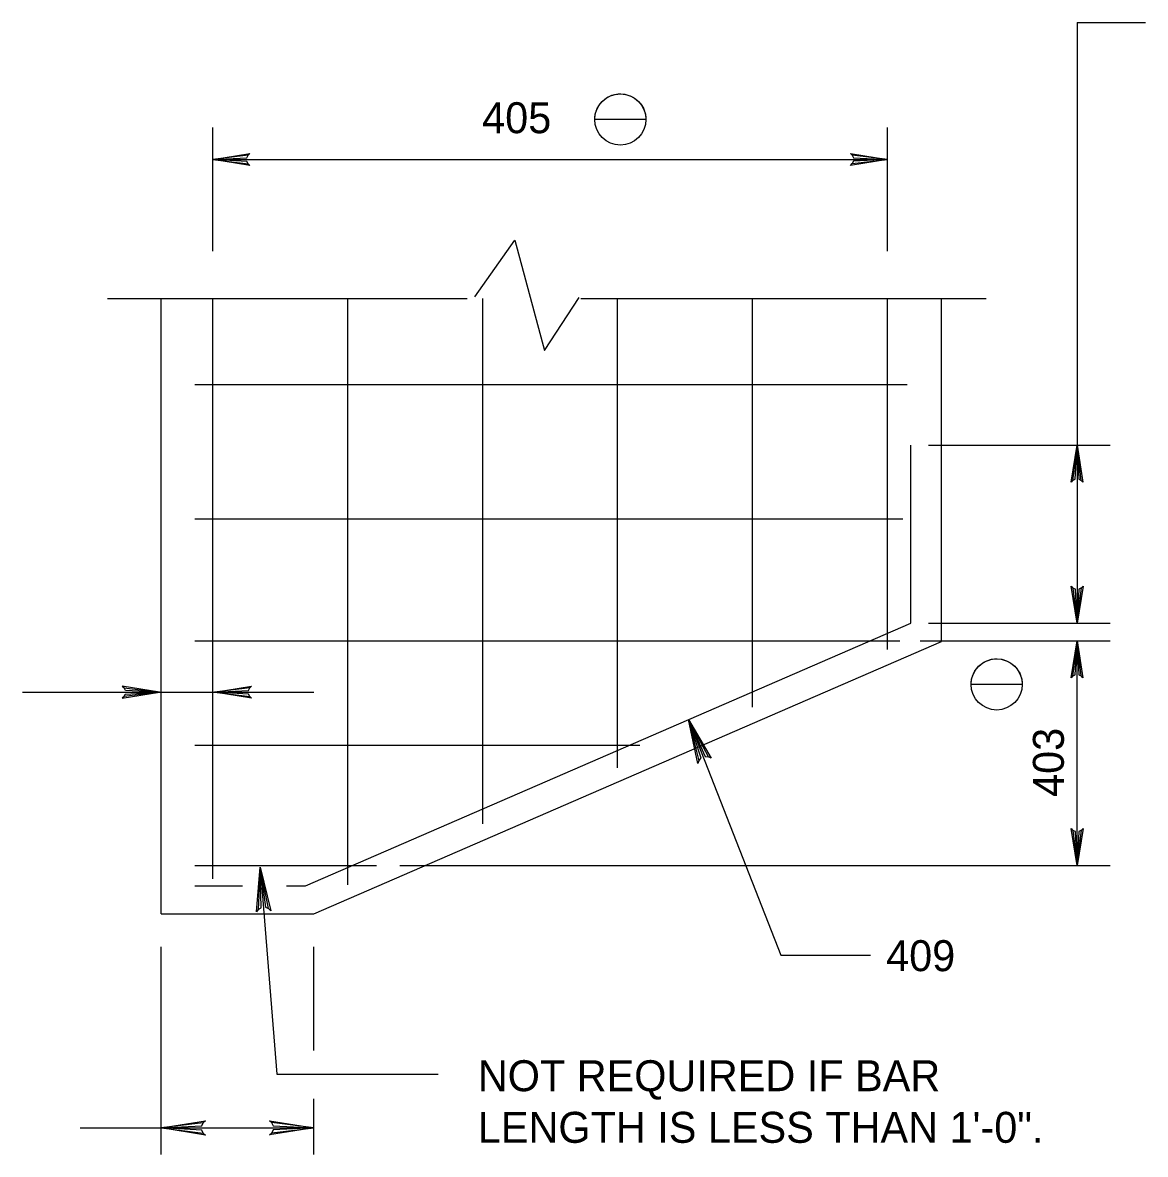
# Model space of a CAD drawing. Extents: x 637933 to 640019, y 298854 to 300042.
# Drawn here: x 638206.9 to 638315.7, y 299000 to 299109.6 of the extents above; entities that cross this region are included whole.
import ezdxf

# ---------------------------------------------------------------- set-up
doc = ezdxf.new("R2010")
doc.units = 0
doc.layers.add('1', color=7, linetype='Continuous')

msp = doc.modelspace()

# ---------------------------------------------------------------- linework, layer by layer
at = {"layer": '1'}
for p, q in [((638309.1, 299109.64), (638309.1, 299051.47)), ((638309.1, 299109.64), (638315.72, 299109.64)), ((638267.33, 299100.26), (638262.37, 299100.26)), ((638225.38, 299087.51), (638225.38, 299099.48)), ((638290.72, 299087.51), (638290.72, 299099.48)), ((638225.38, 299096.38), (638290.72, 299096.38)), ((638215.17, 299082.92), (638250, 299082.92)), ((638220.36, 299023.3), (638220.36, 299082.92)), ((638225.38, 299026.71), (638225.38, 299082.92)), ((638238.45, 299026.11), (638238.45, 299082.92)), ((638251.52, 299032.02), (638251.52, 299082.92)), ((638261.01, 299082.92), (638300.29, 299082.92)), ((638264.58, 299037.44), (638264.58, 299082.92)), ((638277.65, 299043.34), (638277.65, 299082.92)), ((638290.72, 299048.92), (638290.72, 299082.92)), ((638295.96, 299049.68), (638295.96, 299082.92)), ((638223.61, 299074.59), (638292.64, 299074.59)), ((638292.99, 299051.47), (638292.99, 299068.7)), ((638294.71, 299068.7), (638312.3, 299068.7)), ((638223.61, 299061.56), (638292.21, 299061.56)), ((638234.36, 299026.03), (638292.99, 299051.47)), ((638294.71, 299051.47), (638312.3, 299051.47)), ((638223.61, 299049.74), (638291.92, 299049.74)), ((638235.15, 299023.3), (638295.96, 299049.68)), ((638293.89, 299049.74), (638312.3, 299049.74)), ((638309.1, 299028), (638309.1, 299049.74)), ((638206.94, 299044.77), (638235.15, 299044.77)), ((638303.79, 299045.53), (638298.83, 299045.53)), ((638271.44, 299042.12), (638280.4, 299019.31)), ((638223.61, 299039.64), (638266.73, 299039.64)), ((638223.61, 299028), (638241.21, 299028)), ((638230, 299027.44), (638231.57, 299007.77)), ((638243.48, 299028), (638312.3, 299028)), ((638223.61, 299026.03), (638228.25, 299026.03)), ((638232.51, 299026.03), (638234.36, 299026.03)), ((638220.36, 299023.3), (638235.15, 299023.3)), ((638220.36, 299000), (638220.36, 299020.12)), ((638235.15, 299010.07), (638235.15, 299020.12)), ((638280.4, 299019.31), (638289.09, 299019.31)), ((638231.57, 299007.77), (638247.21, 299007.77)), ((638235.15, 299000), (638235.15, 299005.37)), ((638212.52, 299002.57), (638235.15, 299002.57))]:
    msp.add_line(p, q, dxfattribs=at)
for points in [[(638262.37, 299100.26), (638262.39, 299100.55), (638262.44, 299100.82), (638262.51, 299101.07), (638262.61, 299101.31), (638262.75, 299101.57), (638262.9, 299101.79), (638263.09, 299102.01), (638263.34, 299102.23), (638263.61, 299102.41), (638263.84, 299102.53), (638264.02, 299102.6), (638264.29, 299102.68), (638264.65, 299102.74), (638264.91, 299102.74), (638265.27, 299102.71), (638265.59, 299102.63), (638265.86, 299102.53), (638266.13, 299102.39), (638266.33, 299102.25), (638266.57, 299102.05), (638266.77, 299101.84), (638266.94, 299101.6), (638267.08, 299101.36), (638267.17, 299101.15), (638267.26, 299100.85), (638267.32, 299100.53), (638267.33, 299100.26)], [(638228.79, 299095.96), (638228.66, 299096.2), (638225.38, 299096.38), (638228.79, 299095.96), (638228.96, 299095.81), (638225.38, 299096.38), (638228.66, 299096.55), (638228.78, 299096.79), (638225.38, 299096.38), (638228.96, 299096.95), (638228.78, 299096.79)], [(638287.32, 299096.81), (638287.44, 299096.56), (638290.72, 299096.38), (638287.32, 299096.81), (638287.14, 299096.96), (638290.72, 299096.38), (638287.44, 299096.22), (638287.32, 299095.98), (638290.72, 299096.38), (638287.14, 299095.81), (638287.32, 299095.98)], [(638250.74, 299083.09), (638254.64, 299088.56), (638257.51, 299077.89), (638260.86, 299083.02)], [(638308.67, 299065.29), (638308.92, 299065.42), (638309.1, 299068.7), (638308.67, 299065.29), (638308.52, 299065.12), (638309.1, 299068.7), (638309.26, 299065.42), (638309.51, 299065.3), (638309.1, 299068.7), (638309.67, 299065.12), (638309.51, 299065.3)], [(638309.53, 299054.88), (638309.28, 299054.75), (638309.1, 299051.47), (638309.53, 299054.88), (638309.68, 299055.05), (638309.1, 299051.47), (638308.94, 299054.75), (638308.69, 299054.87), (638309.1, 299051.47), (638308.53, 299055.05), (638308.69, 299054.87)], [(638308.67, 299046.34), (638308.92, 299046.46), (638309.1, 299049.74), (638308.67, 299046.34), (638308.52, 299046.16), (638309.1, 299049.74), (638309.26, 299046.47), (638309.51, 299046.35), (638309.1, 299049.74), (638309.67, 299046.16), (638309.51, 299046.35)], [(638298.83, 299045.53), (638298.85, 299045.81), (638298.9, 299046.08), (638298.97, 299046.33), (638299.06, 299046.57), (638299.2, 299046.83), (638299.36, 299047.05), (638299.55, 299047.27), (638299.8, 299047.49), (638300.07, 299047.67), (638300.3, 299047.79), (638300.48, 299047.86), (638300.75, 299047.94), (638301.11, 299048), (638301.37, 299048), (638301.73, 299047.97), (638302.04, 299047.89), (638302.32, 299047.79), (638302.58, 299047.65), (638302.79, 299047.52), (638303.03, 299047.31), (638303.22, 299047.1), (638303.4, 299046.86), (638303.54, 299046.62), (638303.63, 299046.41), (638303.72, 299046.11), (638303.78, 299045.79), (638303.79, 299045.53)], [(638216.77, 299044.35), (638216.89, 299044.6), (638220.19, 299044.78), (638216.77, 299044.35), (638216.59, 299044.2), (638220.19, 299044.78), (638216.9, 299044.94), (638216.78, 299045.19), (638220.19, 299044.78), (638216.59, 299045.35), (638216.78, 299045.19)], [(638228.96, 299044.35), (638228.83, 299044.6), (638225.53, 299044.78), (638228.96, 299044.35), (638229.13, 299044.2), (638225.53, 299044.78), (638228.83, 299044.94), (638228.95, 299045.19), (638225.53, 299044.78), (638229.13, 299045.35), (638228.95, 299045.19)], [(638272.46, 299038.13), (638272.68, 299038.38), (638271.44, 299042.12), (638272.46, 299038.13), (638272.37, 299037.87), (638271.44, 299042.12), (638273.06, 299038.53), (638273.38, 299038.51), (638271.44, 299042.12), (638273.65, 299038.37), (638273.38, 299038.51)], [(638309.53, 299031.4), (638309.28, 299031.28), (638309.1, 299028), (638309.53, 299031.4), (638309.68, 299031.58), (638309.1, 299028), (638308.94, 299031.27), (638308.69, 299031.39), (638309.1, 299028), (638308.53, 299031.58), (638308.69, 299031.39)], [(638229.77, 299023.73), (638230.05, 299023.9), (638229.95, 299027.84), (638229.77, 299023.73), (638229.61, 299023.5), (638229.95, 299027.84), (638230.46, 299023.94), (638230.77, 299023.82), (638229.95, 299027.84), (638230.98, 299023.61), (638230.77, 299023.82)], [(638224.44, 299002.05), (638224.29, 299002.35), (638220.36, 299002.57), (638224.44, 299002.05), (638224.65, 299001.87), (638220.36, 299002.57), (638224.29, 299002.76), (638224.43, 299003.05), (638220.36, 299002.57), (638224.65, 299003.25), (638224.43, 299003.05)], [(638231.06, 299003.08), (638231.22, 299002.78), (638235.15, 299002.57), (638231.06, 299003.08), (638230.85, 299003.26), (638235.15, 299002.57), (638231.22, 299002.37), (638231.07, 299002.08), (638235.15, 299002.57), (638230.85, 299001.88), (638231.07, 299002.08)]]:
    msp.add_lwpolyline(points, dxfattribs=at)
for centre in [(638264.85, 299100.26), (638301.31, 299045.53)]:
    msp.add_circle(centre, 2.48, dxfattribs=at)

# ---------------------------------------------------------------- texts
for s, height, p in [('405', 3, (638251.46, 299098.93)), ('409', 3, (638290.6, 299017.75)), ('NOT REQUIRED IF BAR', 3.0001, (638251.04, 299006.12)), ('LENGTH IS LESS THAN 1\'-0".', 3.0001, (638251.04, 299001.12))]:
    msp.add_text(s, height=height, dxfattribs=at).set_placement(p)
msp.add_text('403', height=3, rotation=90, dxfattribs=at).set_placement((638307.82, 299034.63))

doc.saveas('drawing.dxf')
